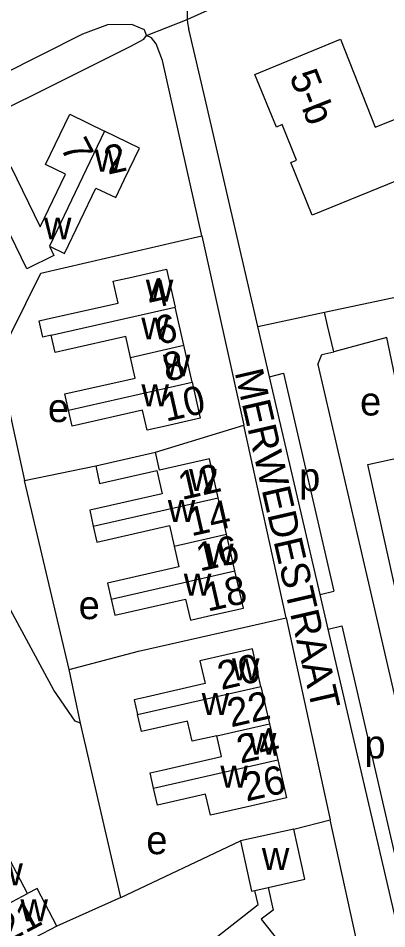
# Model space of a CAD drawing. Extents: x 156721 to 158827, y 386657 to 388950.
# Drawn here: x 157743.6 to 157795.4, y 387600.8 to 387728.9 of the extents above; entities that cross this region are included whole.
import ezdxf

# ---------------------------------------------------------------- set-up
doc = ezdxf.new("R2010")
doc.units = 0
for name, color, linetype in [('BLT_Basislijn', 7, 'Continuous'), ('BLT_Bebouwing', 7, 'Continuous'), ('BLT_Centroide', 7, 'Continuous'), ('BLT_Huisnummer', 7, 'Continuous'), ('BLT_Huisnummer_ tussenligend', 7, 'Continuous'), ('BLT_Huisnummer_reeks', 7, 'Continuous'), ('BLT_Onderverdeling_panden', 7, 'Continuous'), ('BLT_Straatnaam_verkleind', 7, 'Continuous'), ('BLT_Vlakafsluiter', 7, 'Continuous')]:
    doc.layers.add(name, color=color, linetype=linetype)

msp = doc.modelspace()

# ---------------------------------------------------------------- linework, layer by layer
at = {"layer": 'BLT_Basislijn'}
for p, q in [((157767.4, 387728.74), (157808.75, 387747.57)), ((157769.89, 387717.59), (157767.62, 387727.38)), ((157777.33, 387685.57), (157769.89, 387717.59)), ((157769.43, 387698.32), (157775.37, 387671.68)), ((157786.68, 387687.57), (157819.16, 387694.51)), ((157777.33, 387685.57), (157786.68, 387687.57)), ((157787.12, 387685.69), (157786.68, 387687.57)), ((157777.84, 387683.34), (157777.33, 387685.57)), ((157787.98, 387682.01), (157787.12, 387685.69)), ((157778.97, 387678.47), (157777.84, 387683.34)), ((157785.77, 387680.19), (157792.86, 387649.43)), ((157778.97, 387678.47), (157780.92, 387678.97)), ((157786.08, 387647.86), (157778.97, 387678.47)), ((157780.92, 387678.97), (157787.99, 387648.3)), ((157762.94, 387667.86), (157775.37, 387671.68)), ((157781.31, 387644.59), (157775.37, 387671.68)), ((157744.52, 387663.89), (157754.52, 387665.94)), ((157750.78, 387637.28), (157744.52, 387663.89)), ((157786.08, 387647.86), (157787.99, 387648.3)), ((157792.86, 387649.43), (157804, 387601.11)), ((157787.21, 387642.99), (157786.08, 387647.86)), ((157781.31, 387644.59), (157787.48, 387616.14)), ((157787.21, 387642.99), (157789.11, 387643.43)), ((157789.11, 387643.43), (157799.52, 387598.33)), ((157797.55, 387598.49), (157787.21, 387642.99)), ((157752.39, 387629.76), (157750.78, 387637.28)), ((157758.05, 387605.22), (157752.39, 387629.76)), ((157782.36, 387614.86), (157787.48, 387616.14)), ((157758.05, 387605.22), (157774.86, 387613.18)), ((157758.05, 387605.22), (157749.07, 387601.21))]:
    msp.add_line(p, q, dxfattribs=at)
for points in [[(157770.19, 387735.02), (157769.62, 387734.52), (157769.09, 387733.96), (157768.63, 387733.35), (157768.24, 387732.7), (157767.91, 387732.01), (157767.66, 387731.28), (157767.49, 387730.54), (157767.39, 387729.78), (157767.38, 387729.02), (157767.4, 387728.74)], [(157761.67, 387726.47), (157761.36, 387727.29), (157759.58, 387728.03), (157756.17, 387728), (157752.65, 387726.67), (157729.65, 387715.11)], [(157767.4, 387728.74), (157767.44, 387728.26), (157767.59, 387727.5), (157767.62, 387727.38)], [(157729.65, 387710.11), (157759.48, 387725), (157761.29, 387725.95), (157761.67, 387726.47)], [(157769.43, 387698.32), (157763.9, 387722.98), (157763.04, 387725.33), (157762.36, 387726.17), (157761.67, 387726.47)], [(157740.46, 387680.33), (157746.82, 387693.06), (157769.43, 387698.32)], [(157833.52, 387672.88), (157845.96, 387675.73), (157846.58, 387672.97), (157852.64, 387643.3), (157862.53, 387645.04), (157861.23, 387670.09), (157861.4, 387676.24), (157859.02, 387678.72), (157855.93, 387693.47), (157828.83, 387687.41), (157829.77, 387682.41), (157797.29, 387675.24), (157795.45, 387684), (157787.98, 387682.01)], [(157785.77, 387680.19), (157786.32, 387681.62), (157787.98, 387682.01)], [(157740.46, 387680.33), (157741.07, 387679.6), (157744.52, 387663.89)], [(157752.39, 387629.76), (157751.64, 387630.02), (157748.62, 387634.41), (157729.71, 387669.43), (157729.65, 387669.54)], [(157750.78, 387637.28), (157760.54, 387639.87), (157781.31, 387644.59)], [(157736.7, 387594.67), (157740.56, 387586.69), (157756.47, 387565.77), (157760.93, 387568.79), (157769.3, 387575.21), (157792.26, 387593.43), (157792.04, 387595.44), (157787.48, 387616.14)]]:
    msp.add_lwpolyline(points, dxfattribs=at)
at = {"layer": 'BLT_Bebouwing'}
for p, q in [((157748.27, 387684.34), (157765.68, 387688.28)), ((157766.9, 387682.91), (157765.68, 387688.28)), ((157768.07, 387677.74), (157766.9, 387682.91)), ((157754.52, 387665.94), (157762.94, 387667.86)), ((157772.93, 387656.32), (157771.75, 387661.46)), ((157774.1, 387651.16), (157772.93, 387656.32)), ((157777.75, 387634.93), (157778.96, 387629.64)), ((157778.96, 387629.64), (157780.12, 387624.6)), ((157782.36, 387614.86), (157774.86, 387613.18)), ((157744.95, 387605.8), (157742.04, 387611.31))]:
    msp.add_line(p, q, dxfattribs=at)
for points in [[(157776.91, 387721.02), (157788.95, 387725.99), (157793.83, 387713.57), (157801.95, 387716.81)], [(157784.94, 387701.22), (157781.94, 387708.62), (157782.77, 387708.96), (157780.75, 387713.95), (157779.92, 387713.61), (157776.91, 387721.02)], [(157811.26, 387720.52), (157814.21, 387713.13), (157784.94, 387701.22)], [(157746.7, 387699.59), (157750.26, 387706.97), (157747.45, 387708.33), (157750.87, 387715.41), (157755.78, 387713.03)], [(157748.04, 387696.83), (157750.12, 387695.83), (157754.55, 387705.02), (157757.33, 387703.68), (157758.52, 387706.16), (157760.7, 387710.66), (157755.78, 387713.03)], [(157748.04, 387696.83), (157748.66, 387695.55), (157744.82, 387693.68), (157740.92, 387701.69), (157738.73, 387706.19), (157742.58, 387708.06), (157746.7, 387699.59)], [(157747.75, 387686.61), (157757.69, 387688.84), (157756.99, 387691.91), (157759.6, 387692.5), (157764.48, 387693.6), (157765.68, 387688.28)], [(157748.27, 387684.34), (157747.11, 387684.06), (157746.59, 387686.34), (157747.75, 387686.61)], [(157759.42, 387681.21), (157758.76, 387684.13), (157750.46, 387682.26), (157748.82, 387681.88), (157748.26, 387684.34)], [(157750.69, 387673.8), (157750.18, 387676.06), (157760.08, 387678.29), (157759.42, 387681.21)], [(157768.07, 387677.74), (157769.22, 387672.64), (157764.34, 387671.53), (157761.74, 387670.95), (157761.1, 387673.8), (157751.2, 387671.55), (157750.69, 387673.8)], [(157844.76, 387622.28), (157829.98, 387619), (157826.06, 387636.59), (157815.3, 387634.22), (157819.2, 387616.64), (157804.44, 387613.38), (157792.78, 387666.14), (157807.53, 387669.39), (157811.41, 387651.81), (157822.16, 387654.19), (157818.26, 387671.78), (157831.46, 387674.71)], [(157771.75, 387661.46), (157770.51, 387666.93), (157763.51, 387665.34), (157762.94, 387667.86)], [(157754.52, 387665.94), (157755.08, 387663.47), (157763.11, 387665.3), (157763.86, 387662.03), (157753.68, 387659.71), (157754.19, 387657.46)], [(157754.19, 387657.46), (157754.7, 387655.21), (157764.89, 387657.54), (157765.55, 387654.63)], [(157765.55, 387654.63), (157766.21, 387651.74), (157756.2, 387649.45), (157756.7, 387647.19)], [(157756.7, 387647.19), (157757.22, 387644.94), (157767.16, 387647.2), (157767.83, 387644.24), (157770.42, 387644.83), (157775.29, 387645.94), (157774.1, 387651.16)], [(157777.75, 387634.93), (157776.55, 387640.19), (157769.17, 387638.5), (157769.3, 387637.9), (157769.9, 387635.33), (157761.6, 387633.43), (157759.92, 387633.04), (157760.39, 387630.96)], [(157771.57, 387627.95), (157768.08, 387627.2), (157767.43, 387630.04), (157760.94, 387628.56), (157760.39, 387630.96)], [(157762.67, 387620.61), (157762.18, 387622.76), (157763.85, 387623.14), (157772.23, 387625.06), (157771.57, 387627.95)], [(157780.12, 387624.6), (157781.35, 387619.25), (157776.47, 387618.13), (157770.66, 387616.8), (157769.98, 387619.75), (157763.22, 387618.2), (157762.67, 387620.6)], [(157778.75, 387606.63), (157783.94, 387607.79), (157782.36, 387614.86)], [(157774.86, 387613.18), (157776.44, 387606.12), (157776.9, 387606.22)], [(157749.07, 387601.21), (157746.28, 387606.5), (157744.95, 387605.8)], [(157772.66, 387598.58), (157771.7, 387599.8), (157777.34, 387604.26), (157776.9, 387606.22)], [(157778.75, 387606.63), (157779.45, 387603.45), (157777.79, 387602.16), (157783.83, 387594.54), (157779.05, 387590.76)], [(157749.07, 387601.21), (157746.03, 387599.59), (157741.61, 387597.24)]]:
    msp.add_lwpolyline(points, dxfattribs=at)
at = {"layer": 'BLT_Onderverdeling_panden'}
for p, q in [((157755.78, 387713.03), (157748.04, 387696.83)), ((157759.42, 387681.21), (157766.9, 387682.91)), ((157750.69, 387673.8), (157768.07, 387677.74)), ((157754.19, 387657.46), (157771.75, 387661.46)), ((157765.55, 387654.63), (157772.93, 387656.32)), ((157756.7, 387647.19), (157774.1, 387651.16)), ((157760.39, 387630.96), (157777.75, 387634.93)), ((157771.57, 387627.95), (157778.96, 387629.64)), ((157762.67, 387620.61), (157780.12, 387624.6)), ((157776.9, 387606.22), (157778.75, 387606.63)), ((157738.8, 387602.54), (157744.95, 387605.8))]:
    msp.add_line(p, q, dxfattribs=at)
at = {"layer": 'BLT_Vlakafsluiter'}
msp.add_line((157761.67, 387726.47), (157767.4, 387728.74), dxfattribs=at)

# ---------------------------------------------------------------- texts
at = {"layer": 'BLT_Centroide'}
for s, p in [('w', (157754.38, 387707.34)), ('w', (157747.25, 387697.81)), ('w', (157761.57, 387689.06)), ('w', (157760.93, 387683.73)), ('w', (157763.96, 387678.53)), ('w', (157760.95, 387674.34)), ('e', (157747.8, 387672.11)), ('e', (157791.69, 387673.03)), ('w', (157767.65, 387662.41)), ('p', (157783.11, 387662.4)), ('w', (157764.66, 387658.06)), ('w', (157770.05, 387651.94)), ('w', (157766.91, 387647.69)), ('e', (157752.13, 387644.38)), ('w', (157773.68, 387635.78)), ('w', (157769.43, 387630.91)), ('w', (157776.06, 387625.31)), ('p', (157792.3, 387624.79)), ('w', (157772.05, 387620.69)), ('e', (157761.64, 387611.32)), ('w', (157777.88, 387609.11)), ('w', (157740.41, 387606.94)), ('w', (157743.94, 387601.88))]:
    msp.add_text(s, height=4, dxfattribs=at).set_placement(p)
at = {"layer": 'BLT_Huisnummer'}
for s, rotation, p in [('7', 296.8521, (157749.49, 387710.79)), ('2', 12.7464, (157756.23, 387706.89)), ('4', 12.7493, (157762.21, 387687.99)), ('10', 12.7448, (157764.4, 387672.15)), ('12', 12.8515, (157766.63, 387661.12)), ('18', 12.8408, (157770.25, 387645.42)), ('20', 12.8937, (157772.17, 387634.4)), ('26', 12.8881, (157775.69, 387618.71)), ('21', 27.9795, (157742.02, 387598.76))]:
    msp.add_text(s, height=4, rotation=rotation, dxfattribs=at).set_placement(p)
at = {"layer": 'BLT_Huisnummer_ tussenligend'}
for s, rotation, p in [('6', 12.7493, (157763.38, 387682.93)), ('8', 12.7493, (157764.45, 387677.76)), ('14', 12.8515, (157767.96, 387656.02)), ('16', 12.8515, (157769.16, 387651.07)), ('22', 12.8937, (157773.54, 387629.15)), ('24', 12.8937, (157774.87, 387624.05))]:
    msp.add_text(s, height=4, rotation=rotation, dxfattribs=at).set_placement(p)
at = {"layer": 'BLT_Huisnummer_reeks'}
msp.add_text('5-b', height=4, rotation=291.4348, dxfattribs=at).set_placement((157781.7, 387720.78))
at = {"layer": 'BLT_Straatnaam_verkleind'}
msp.add_text('MERWEDESTRAAT', height=4, rotation=282.9507, dxfattribs=at).set_placement((157774.04, 387679.12))

doc.saveas('drawing.dxf')
